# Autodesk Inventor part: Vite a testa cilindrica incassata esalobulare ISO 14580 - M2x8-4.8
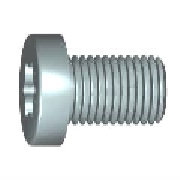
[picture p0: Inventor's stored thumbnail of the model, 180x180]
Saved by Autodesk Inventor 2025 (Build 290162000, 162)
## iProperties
Created: 2024-01
Part Number: Vite a testa cilindrica incassata esalobulare ISO 14580 - M2x8-4.8
Material: Acciaio
Description: ISO 14580 - Viti a testa cilindrica incassata esalobulare - Seconda edizione
Document SubType Name: Modeling
Standard: 14580
Designer: Ryzen5700u
Standards Organization: ISO
Language: it-IT
Size Designation: M2x8-4.8
Categories: <MemberInstance><Categories><Category DisplayName="Elementi di fissaggio" InternalName="e4da775c-781d-43d5-af7c-5136215cf5a6" Mnemonic="FSTN"><Category DisplayN
Density: 7.85 g/cm^3
Appearance: Lamiera
IsCustomPart: 0
Author: Ryzen5700u
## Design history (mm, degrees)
revolve "Revolution1" stored, may be unused: angle "d4" = 90 deg
thread "Thread1" dims "d6" = 8 (= b), "d7" = 0
sketch "Sketch2" dims "d21" = 1.75 (= A_)
  geometry: L1 (-0.53, -0.306)-(-0.875, 0); L2 (0, 0)-(-0.53, -0.306); L3 (0, 0)-(-0.53, 0.306); L4 (-2.85, 0)-(2.85, 0) reference; L5 (-0.875, 0)-(-0.53, 0.306); A1 r 0.613 centre (0, 0) between (-0.53, -0.306) and (-0.53, 0.306); 2 further points
  constraints: 8 end point, 2 coincident, 2 point on circle, 1 centre point, 1 horizontal alignment, 1 point on line, 2 other
  dimensions: "d19" = 60 deg angle of L3 L2; "d20" = 30 deg angle of L3 L4 (= 0.5 x d19); "d26" = 1.225 diameter of A1 (= 0.7 x d21)
extrude "Extrusion1" cut sketch "Sketch2" distance "d27" = 0.84 (= t); taper "d28" = 0 deg
pattern_circular "Circular Pattern1" dims angle "d30" = 360 deg
fillet "Fillet2" dims "d32" = 0.2 (= v)
fillet "Fillet3" dims "d33" = 0.2 (= v)
fillet "Fillet5" dims "d35" = 0.1 (= r)
chamfer "Chamfer2" distance "d36" = 0.2 (= v); stored, may be unused: second distance "d37" = 2, angle "d38" = 45 deg
body "Solid1"
sketch "Sketch1"
  geometry: L1 (0, 0)-(8, 0); L2 (8, 0)-(8, 1); L3 (8, 1)-(0, 1); L4 (0, 1)-(0, 0); L5 (0, 0)-(-1.55, 0); L6 (-1.55, 0)-(-1.55, 1.9); L7 (-1.55, 1.9)-(0, 2.036); L8 (0, 2.036)-(0, 0)
  constraints: 16 end point, 3 parallel, 2 horizontal, 2 perpendicular
  dimensions: "d0" = 2 diameter of L3 L1 (= d); "d3" = 8 distance of L2.end L3.end (= l_); "d46" = 85 deg angle of L8 L7; "d47" = 1.55 distance between parallel lines of L8 L6 (= k); "d49" = 3.8 diameter of L6.end L1 (= dk)
other parameters: "A_" = 1.75 [user parameter; used in 1 equation term], "d" = 2 [user parameter; used in 2 equation terms], "dk" = 3.8 [user parameter; used in 1 equation term], "k" = 1.55 [user parameter; used in 1 equation term], "l_" = 8 [user parameter; used in 2 equation terms], "lg" = 0 [user parameter; used in 1 equation term], "t" = 0.84 [user parameter; used in 1 equation term], "w" = 0.55 [user parameter], "v" = 0.2 [user parameter; used in 3 equation terms], "r" = 0.1 [user parameter; used in 1 equation term], "da" = 2.6 [user parameter], "ds_" = 2 (= d) [user parameter], "ls" = 0 [user parameter], "b" = 8 (= l_ - lg) [user parameter; used in 1 equation term], "d42" = 0, "d43" = 0, "d44" = 0, "p" = 0.4 [user parameter]
